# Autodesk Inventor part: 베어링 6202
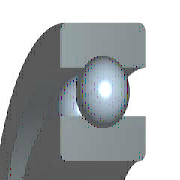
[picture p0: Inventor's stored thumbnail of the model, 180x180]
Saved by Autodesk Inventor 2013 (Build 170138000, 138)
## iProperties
Created: 2012-02
Part Number: 베어링 6202
Material: 강철, 연강
Description: 깊은 그루브 볼 베어링
Document SubType Name: Modeling
Standard: KS B 2023
Designer: mduedu
Standards Organization: KS
Language: ko-KR
Size Designation: 6202 - 15 x 35 x 11
Categories: <MemberInstance><Categories><Category DisplayName="샤프트 부품" InternalName="7f7aeb1f-a693-4053-b835-cee3144e0d98" Mnemonic="SHFT"><Category DisplayName="베어링" Inter
Density: 1 g/cm^3
IsCustomPart: 1
Author: mduedu
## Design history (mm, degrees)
sketch "스케치" dims "d0" = 5.2 (= -0.26 x WD + 0.26 x BD)
  geometry: L1 (2.9, 12.5)-(8.1, 12.5); L2 (5.5, 12.5)-(5.5, 9.9); L3 (5.5, 12.5)-(5.5, 15.1); L4 (3.568, 10.76)-(0, 10.76); L5 (0, 7.5)-(11, 7.5); L6 (3.568, 14.24)-(0, 14.24); L7 (0, 17.5)-(11, 17.5); L8 (11, 7.5)-(11, 10.76); L9 (7.432, 10.76)-(11, 10.76); L10 (7.432, 14.24)-(11, 14.24); L11 (11, 17.5)-(11, 14.24); L12 (-1.4, 0)-(8.4, 0) reference; L13 (0, -0.3)-(0, 5.3) reference
  constraints: 22 end point, 4 point on line, 2 collinear, 2 perpendicular, 2 symmetric about line, 1 midpoint, 1 parallel, 14 other
  dimensions: "d9" = 15 diameter of L5 L12 (= WD); "d11" = 35 diameter of L7 L12 (= BD); "d12" = 11 distance between parallel lines of L8 L13 (= KB); "d13" = 21.52 diameter of L9 L12 (= 0.326 x BD + 0.674 x WD)
revolve "본체" stored, may be unused: angle "d6" = 90 deg
revolve "볼" stored, may be unused: angle "d7" = 90 deg
pattern_circular "IDS_ARRAYBALL[SIMPL:T]" dims angle "d3" = 360 deg
body "Solid1"
fillet "모깎기1" dims "d1" = 0.6 (= KRS)
other parameters: "WD" = 15 [user parameter; used in 5 equation terms], "BD" = 35 [user parameter; used in 5 equation terms], "KB" = 11 [user parameter; used in 1 equation term], "KRS" = 0.6 [user parameter; used in 1 equation term], "d4" = 0, "d5" = 0, "d8" = 0, "d14" = 0, "d15" = 0, "BBA" = 0 [user parameter], "BC0" = 3750000 [user parameter], "BC" = 7800000 [user parameter], "BR" = 17.5 (= 0.5 x BD) [user parameter], "WR" = 7.5 (= 0.5 x WD) [user parameter]
